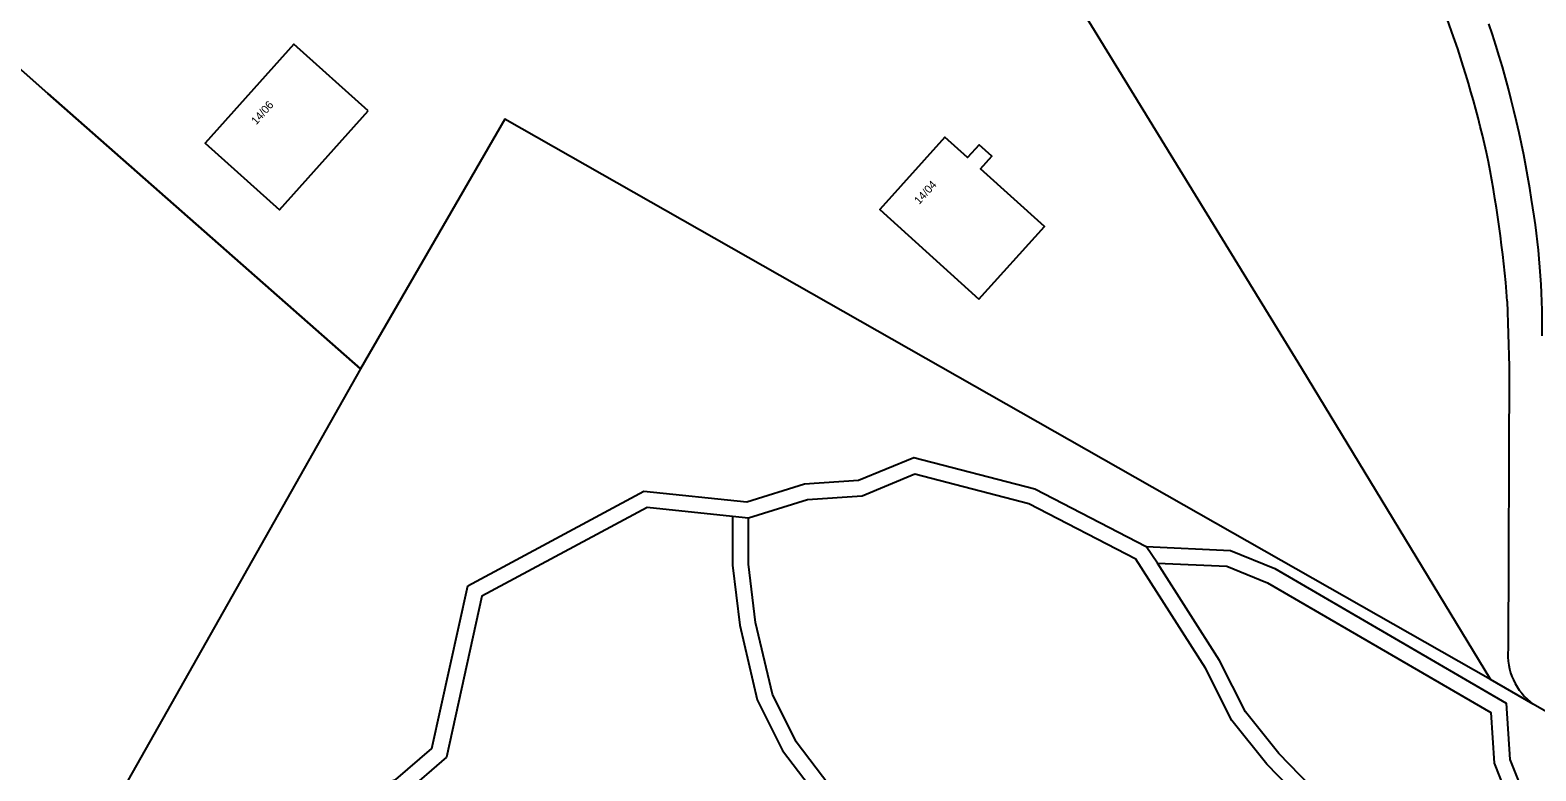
# Model space of a CAD drawing. Extents: x 157154 to 159278, y 385000 to 386650.
# Drawn here: x 157880.2 to 158068.3, y 385890.8 to 385983.3 of the extents above; entities that cross this region are included whole.
import ezdxf

# ---------------------------------------------------------------- set-up
doc = ezdxf.new("R2010")
doc.units = 0
for name, color, linetype in [('IMGEO_Gemengd_bos', 7, 'Continuous'), ('IMGEO_Groenvoorziening', 7, 'Continuous'), ('IMGEO_Hek', 7, 'Continuous'), ('IMGEO_Pand', 7, 'Continuous'), ('IMGEO_Pand_nummerreeks', 7, 'Continuous'), ('IMGEO_Voetpad_halfverhard', 7, 'Continuous')]:
    doc.layers.add(name, color=color, linetype=linetype)

msp = doc.modelspace()

# ---------------------------------------------------------------- linework, layer by layer
at = {"layer": 'IMGEO_Gemengd_bos'}
for points in [[(157923.9, 386092.49), (157974.24, 386046.68), (158002.86, 386000), (158038.99, 385941.05), (158062.63, 385902.16)], [(158067.95, 385899.1), (158062.63, 385902.16)]]:
    msp.add_lwpolyline(points, dxfattribs=at)
at = {"layer": 'IMGEO_Groenvoorziening'}
for points in [[(157921.45, 385940.96), (157882.35, 385975.36), (157854.58, 386000), (157840.47, 386012.79), (157874.62, 386045.41)], [(158062.63, 385902.16), (157939.45, 385972.14), (157921.45, 385940.96)], [(157921.45, 385940.96), (157892.38, 385889.57), (157869.06, 385848.74), (157801.31, 385887.35), (157749.19, 385916.71), (157748.99, 385916.39), (157748.86, 385916.17)]]:
    msp.add_lwpolyline(points, dxfattribs=at)
at = {"layer": 'IMGEO_Hek'}
for points in [[(157840.47, 386012.79), (157854.58, 386000), (157882.35, 385975.36), (157921.45, 385940.96)], [(157921.45, 385940.96), (157892.38, 385889.57), (157869.06, 385848.74)]]:
    msp.add_lwpolyline(points, dxfattribs=at)
at = {"layer": 'IMGEO_Pand'}
for points in [[(157922.37, 385973.18), (157913.08, 385981.49), (157902.02, 385969.13), (157911.31, 385960.82), (157922.37, 385973.18)], [(157998.69, 385949.68), (158006.87, 385958.75), (157998.91, 385965.93), (158000.33, 385967.51), (157998.74, 385968.95), (157997.29, 385967.33), (157994.45, 385969.89), (157986.3, 385960.85), (157998.69, 385949.68)]]:
    msp.add_lwpolyline(points, dxfattribs=at)
at = {"layer": 'IMGEO_Voetpad_halfverhard'}
for points in [[(158064.71, 385949.43), (158064.94, 385941.26), (158064.82, 385905.95)], [(157884.64, 385838.82), (157884.72, 385839.09), (157888.34, 385851.23), (157897.07, 385869.34), (157905.88, 385879.01), (157915.07, 385885.91), (157925.86, 385889.66), (157930.36, 385893.56), (157934.85, 385913.88), (157956.82, 385925.7), (157969.71, 385924.35), (157976.91, 385926.6), (157983.66, 385927.05), (157990.55, 385929.9), (158005.67, 385925.97), (158019.61, 385918.77)], [(158055.9, 385869.73), (158034.68, 385891.6), (158030.3, 385897.04), (158027.01, 385903.57), (158018.32, 385917.19), (158004.95, 385924.09), (157990.7, 385927.8), (157984.12, 385925.08), (157977.28, 385924.62), (157969.92, 385922.32)], [(157967.92, 385922.53), (157957.23, 385923.65), (157936.61, 385912.56), (157932.17, 385892.48), (157926.88, 385887.9), (157917.89, 385884.78)], [(157969.92, 385922.32), (157967.92, 385922.53)], [(157967.92, 385922.53), (157967.92, 385916.45), (157968.82, 385908.94), (157971.01, 385899.64), (157974.14, 385893.32), (157980.71, 385884.71), (157982.05, 385882.41), (157982.55, 385879.92), (157982.48, 385876.19), (157981.86, 385869.93), (157982.56, 385866.68), (157984.91, 385863.3), (157987.71, 385860.6), (157991.64, 385858.28), (157996.62, 385857.01), (158000.38, 385855.79), (158003.65, 385854.05), (158018.37, 385843.43), (158023.06, 385841.22), (158030.2, 385838.69)], [(158042.55, 385836.11), (158025.81, 385842.14), (158019.39, 385845.16), (158004.71, 385855.75), (158001.17, 385857.64), (157997.18, 385858.93), (157992.41, 385860.15), (157988.93, 385862.2), (157985.66, 385864.98), (157984.64, 385866.77), (157984.6, 385867.25), (157984.38, 385869.9), (157984.52, 385871.08), (157985.22, 385876.8), (157985.24, 385877.7), (157985.18, 385880.91), (157984.17, 385883.47), (157975.85, 385894.38), (157972.9, 385900.32), (157970.8, 385909.29), (157969.92, 385916.57), (157969.92, 385922.32)], [(158019.61, 385918.77), (158030.11, 385918.28), (158035.65, 385916.03), (158064.59, 385899.23), (158065.04, 385892.17), (158069.76, 385880.32), (158059.11, 385869.37)], [(158021, 385916.7), (158019.61, 385918.77)], [(158057.68, 385870.76), (158036.18, 385892.93), (158031.99, 385898.12), (158028.75, 385904.56), (158021, 385916.7)], [(158021, 385916.7), (158029.67, 385916.3), (158034.77, 385914.23), (158062.66, 385898.03), (158063.06, 385891.73), (158067.42, 385880.79), (158057.68, 385870.76)], [(158105.5, 385877.57), (158078.34, 385893.15), (158067.95, 385899.1)]]:
    msp.add_lwpolyline(points, dxfattribs=at)
for centre, radius, start, end in [((157934.8, 385939.53), 130.45, 12.5947, 20.4545), ((157939.5, 385942.65), 129.7, 8.6355, 18.6126), ((157914.48, 385937.91), 150.67, 4.3831, 11.5094), ((157977.16, 385946.5), 91.91, 359.1234, 9.7878), ((158072.36, 385905.26), 7.57, 174.8119, 234.4225)]:
    msp.add_arc(centre, radius, start, end, dxfattribs=at)

# ---------------------------------------------------------------- texts
at = {"layer": 'IMGEO_Pand_nummerreeks'}
for s, rotation, p in [('14/06', 48.2415, (157908.41, 385971.37)), ('14/04', 47.6698, (157991.24, 385961.42))]:
    msp.add_text(s, height=1, rotation=rotation, dxfattribs=at).set_placement(p)

doc.saveas('drawing.dxf')
